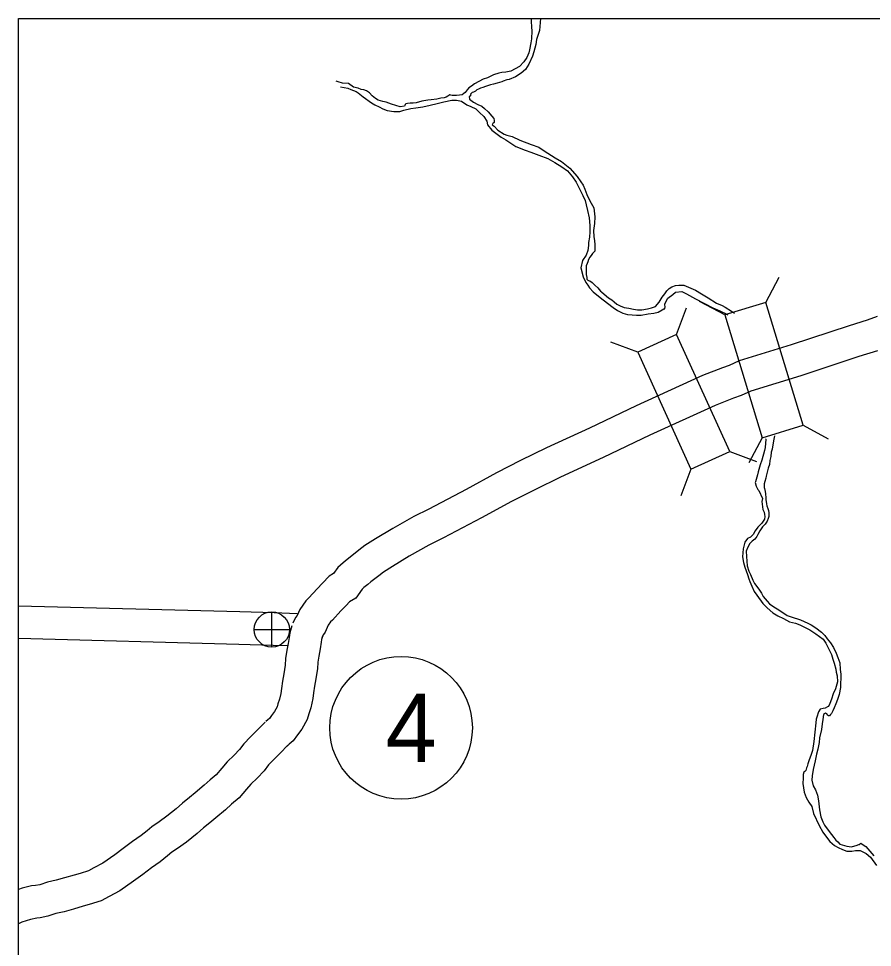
# Model space of a CAD drawing. Extents: x 79818 to 83933, y 50884 to 53307.
# Drawn here: x 80798.6 to 80904, y 53079 to 53193.5 of the extents above; entities that cross this region are included whole.
import ezdxf

# ---------------------------------------------------------------- set-up
doc = ezdxf.new("R2010")
doc.units = 0
for name, color, linetype in [('Level 10', 7, 'Continuous'), ('Level 20', 7, 'Continuous'), ('Level 26', 7, 'Continuous'), ('Level 27', 7, 'Continuous'), ('Level 9', 7, 'Continuous'), ('R_No Plot', 7, 'Continuous')]:
    doc.layers.add(name, color=color, linetype=linetype)

msp = doc.modelspace()

# ---------------------------------------------------------------- linework, layer by layer
at = {"layer": 'Level 10'}
for points in [[(80904.56, 53156.76), (80903.34, 53156.32), (80901.12, 53155.64), (80893.95, 53153.27), (80887.56, 53151.32), (80886.31, 53150.74), (80885.47, 53150.45), (80883.02, 53149.49), (80874.83, 53145.77), (80869.07, 53143.01), (80863.77, 53140.56), (80860.54, 53139), (80857.58, 53137.5), (80853.85, 53135.45), (80849.25, 53133.02), (80847.37, 53132.1), (80844.79, 53130.63), (80842.66, 53129.34), (80841.36, 53128.54), (80840.61, 53127.96)], [(80904.6, 53152.53), (80902.33, 53151.83), (80895.16, 53149.46), (80889, 53147.58), (80887.81, 53147.02), (80886.84, 53146.69), (80884.57, 53145.81), (80876.52, 53142.14), (80870.77, 53139.39), (80865.48, 53136.94), (80862.32, 53135.41), (80859.45, 53133.96), (80855.74, 53131.93), (80851.07, 53129.46), (80849.24, 53128.56), (80846.82, 53127.19), (80844.74, 53125.92), (80843.64, 53125.25), (80843.07, 53124.8)], [(80840.61, 53127.96), (80839.51, 53127.1), (80839.17, 53126.8), (80838.65, 53126.39), (80838.01, 53125.8), (80837.48, 53125.06), (80836.92, 53124.73), (80836.12, 53123.9), (80835.46, 53123.2), (80834.44, 53122.08), (80834.05, 53121.7), (80833.3, 53120.64), (80832.98, 53119.89), (80832.8, 53119.66), (80832.45, 53118.93)], [(80843.07, 53124.8), (80842.09, 53124.04), (80841.73, 53123.72), (80841.23, 53123.33), (80841.03, 53123.14), (80840.24, 53122.05), (80839.43, 53121.57), (80839.02, 53121.13), (80838.39, 53120.48), (80837.33, 53119.31), (80837.11, 53119.09), (80836.82, 53118.68), (80836.46, 53117.84), (80836.22, 53117.53), (80836.05, 53117.19)], [(80830.15, 53120.21), (80825.91, 53120.33), (80798.6, 53121.06)], [(80832.99, 53120.11), (80830.17, 53120.21)], [(80832.33, 53118.6), (80832.09, 53117.74), (80832.01, 53117.17), (80831.89, 53116.45), (80831.73, 53115.61), (80831.55, 53114.58), (80831.51, 53113.77), (80831.41, 53113.24), (80831.33, 53112.69), (80831.19, 53111.81), (80831.04, 53110.89), (80830.98, 53110.29), (80830.82, 53109.57), (80830.62, 53108.98), (80830.51, 53108.62), (80830.19, 53108.03), (80829.84, 53107.56), (80829.56, 53107.19), (80829.38, 53107.04), (80829.13, 53106.82)], [(80830.04, 53116.21), (80825.8, 53116.33), (80798.6, 53117.05)], [(80836.18, 53117.51), (80836.01, 53116.93), (80835.97, 53116.59), (80835.83, 53115.76), (80835.67, 53114.88), (80835.53, 53114.12), (80835.49, 53113.3), (80835.36, 53112.61), (80835.29, 53112.09), (80835.14, 53111.17), (80835.01, 53110.36), (80834.93, 53109.65), (80834.68, 53108.49), (80834.42, 53107.75), (80834.22, 53107.08), (80833.58, 53105.87), (80833.04, 53105.16), (80832.5, 53104.45), (80832, 53104.01), (80831.75, 53103.79)], [(80831.79, 53116.15), (80830.02, 53116.21)], [(80829.03, 53106.73), (80828.04, 53105.75), (80827.22, 53104.91), (80826.41, 53104.07), (80825.87, 53103.35), (80825.2, 53102.66), (80824.35, 53101.83), (80823.7, 53101.06), (80822.99, 53100.24), (80822.26, 53099.61), (80821.52, 53098.96), (80820.4, 53098.01), (80819.68, 53097.43), (80818.85, 53096.75), (80818.04, 53096.04), (80816.92, 53095.12), (80815.95, 53094.46), (80815.07, 53093.84), (80814.47, 53093.33), (80813.73, 53092.74), (80812.65, 53092.02), (80811.53, 53091.14), (80810.47, 53090.38), (80808.99, 53089.35), (80807.9, 53088.76), (80807.24, 53088.4), (80806.19, 53088.06), (80805.48, 53087.87), (80804.28, 53087.52), (80803.25, 53087.24), (80802.16, 53086.98), (80801.22, 53086.68), (80800.69, 53086.57), (80800.18, 53086.53), (80799.03, 53086.24), (80798.6, 53086.11)], [(80831.85, 53103.88), (80830.88, 53102.93), (80830.09, 53102.12), (80829.46, 53101.47), (80828.92, 53100.75), (80828.04, 53099.84), (80827.28, 53099.1), (80826.73, 53098.46), (80825.83, 53097.41), (80824.9, 53096.6), (80824.14, 53095.93), (80822.96, 53094.93), (80822.2, 53094.32), (80821.43, 53093.69), (80820.63, 53092.99), (80819.32, 53091.92), (80818.23, 53091.17), (80817.53, 53090.68), (80817, 53090.23), (80816.09, 53089.51), (80815, 53088.77), (80813.93, 53087.95), (80812.79, 53087.12), (80811.09, 53085.94), (80809.8, 53085.23), (80808.8, 53084.71), (80807.33, 53084.23), (80806.57, 53084.02), (80805.37, 53083.67), (80804.23, 53083.36), (80803.22, 53083.12), (80802.23, 53082.81), (80801.27, 53082.61), (80800.84, 53082.57), (80800.09, 53082.38), (80799.55, 53082.22), (80799.02, 53082.07), (80798.68, 53081.92), (80798.6, 53081.88)]]:
    msp.add_lwpolyline(points, dxfattribs=at)
at = {"layer": 'Level 20'}
for p, q in [((80890.82, 53158.51), (80892.47, 53161.61)), ((80885.77, 53156.97), (80882.66, 53158.62)), ((80879.82, 53154.54), (80881.06, 53157.84)), ((80875.02, 53152.36), (80871.72, 53153.59)), ((80895.44, 53143.36), (80898.55, 53141.7)), ((80890.39, 53141.82), (80888.73, 53138.71)), ((80886.38, 53140.13), (80889.68, 53138.89)), ((80881.58, 53137.94), (80880.35, 53134.64))]:
    msp.add_line(p, q, dxfattribs=at)
for points in [[(80885.77, 53156.97), (80890.39, 53141.82), (80895.44, 53143.36), (80890.82, 53158.51)], [(80886.38, 53140.13), (80879.82, 53154.54), (80875.02, 53152.36), (80881.58, 53137.94)]]:
    msp.add_lwpolyline(points, close=True, dxfattribs=at)
at = {"layer": 'Level 26'}
for p, q in [((80829.86, 53115.99), (80829.86, 53120.32)), ((80827.69, 53118.16), (80832.02, 53118.16))]:
    msp.add_line(p, q, dxfattribs=at)
msp.add_circle((80829.86, 53118.16), 2.17, dxfattribs=at)
at = {"layer": 'Level 27'}
msp.add_circle((80845.81, 53106.04), 8.8, dxfattribs=at)
at = {"layer": 'Level 9'}
for points in [[(80861.86, 53193.52), (80861.87, 53193.2), (80861.91, 53192.46), (80861.95, 53192.02), (80861.93, 53191.02), (80861.81, 53190.52), (80861.67, 53189.68), (80861.59, 53189.28), (80861.35, 53188.7), (80860.97, 53188.19), (80860.42, 53187.61), (80859.37, 53187.03), (80858.75, 53186.89), (80858.24, 53186.85), (80857.88, 53186.79), (80857.23, 53186.57), (80856.49, 53186.2), (80855.96, 53186.05), (80855.41, 53185.77), (80854.88, 53185.47), (80854.5, 53185.2), (80854.16, 53184.96), (80853.96, 53184.73), (80853.73, 53184.41), (80853.55, 53184.26), (80853.34, 53184.13), (80853.01, 53184.08), (80852.64, 53184.02), (80852.12, 53184.05), (80851.96, 53184.08), (80851.82, 53184.1), (80851.59, 53183.93), (80851.37, 53183.82), (80851.15, 53183.75), (80850.72, 53183.69), (80850.23, 53183.58), (80849.51, 53183.5), (80849.11, 53183.44), (80848.37, 53183.33), (80847.66, 53183.12), (80847.3, 53183.08), (80846.94, 53183.1), (80846.59, 53183.06), (80846.39, 53183), (80846.29, 53182.89), (80846.31, 53182.87), (80846.23, 53182.73), (80845.72, 53182.63), (80845.18, 53182.81), (80844.65, 53182.98), (80843.96, 53183.2), (80843.56, 53183.29), (80843, 53183.47), (80842.66, 53183.66), (80842.26, 53183.99), (80841.93, 53184.36), (80841.55, 53184.6), (80841.22, 53184.73), (80840.87, 53184.79), (80840.52, 53184.92), (80839.96, 53185.05), (80839.34, 53185.52), (80838.57, 53185.56), (80838.05, 53185.71), (80837.79, 53185.81)], [(80863.02, 53193.52), (80862.92, 53192.07), (80862.53, 53190.94), (80862.45, 53190.31), (80862.19, 53189.43), (80862.05, 53188.87), (80861.58, 53187.91), (80861.19, 53187.23), (80860.65, 53186.78), (80859.95, 53186.35), (80859.14, 53186), (80858.85, 53185.97), (80858.41, 53185.78), (80858.23, 53185.7), (80857.67, 53185.55), (80857.23, 53185.43), (80856.86, 53185.34), (80856.5, 53185.24), (80856.22, 53185.14), (80855.92, 53185.02), (80855.6, 53184.92), (80855.35, 53184.83), (80855.17, 53184.72), (80854.98, 53184.58), (80854.74, 53184.44), (80854.59, 53184.4), (80854.49, 53184.32), (80854.39, 53184.21), (80854.41, 53184.11), (80854.21, 53183.88), (80854.24, 53183.62), (80854.24, 53183.57), (80854.75, 53183.23), (80855.28, 53182.94), (80855.79, 53182.7), (80856.12, 53182.42), (80856.55, 53182), (80857, 53181.47), (80857.27, 53181.18), (80857.31, 53180.95), (80857.32, 53180.72), (80857.25, 53180.67), (80857.14, 53180.59), (80857.04, 53180.43), (80857.32, 53180.24), (80857.75, 53179.74), (80858.52, 53179.28), (80858.88, 53179.15), (80859.52, 53178.96), (80860.49, 53178.52), (80861.88, 53177.97), (80862.82, 53177.64), (80863.46, 53177.21), (80864.83, 53176.33), (80865.61, 53175.88), (80866.65, 53175.08), (80867.54, 53174.04), (80868, 53173.39), (80868.29, 53172.99), (80868.51, 53172.49), (80868.74, 53171.81), (80869.11, 53171.02), (80869.59, 53170.18), (80869.74, 53169.06), (80869.67, 53168.25), (80869.58, 53167.4), (80869.62, 53166.59), (80869.69, 53166.13), (80869.74, 53165.63), (80869.73, 53165.23), (80869.71, 53164.85), (80869.46, 53164.54), (80869.26, 53164.31), (80869.1, 53164.11), (80868.96, 53163.82), (80868.87, 53163.52), (80868.78, 53163.32), (80868.68, 53163.02), (80868.65, 53162.76), (80868.64, 53162.54), (80868.65, 53162.32), (80868.68, 53161.96), (80868.74, 53161.6), (80868.75, 53161.37), (80868.85, 53161.25), (80868.94, 53161.23), (80869.13, 53161.17), (80869.38, 53160.96), (80869.73, 53160.63), (80870.1, 53160.32), (80870.44, 53159.88), (80870.54, 53159.8), (80871.15, 53159.26), (80871.43, 53159.08), (80871.84, 53158.82), (80872.13, 53158.58), (80872.44, 53158.3), (80872.84, 53158.07), (80873.34, 53157.87), (80873.91, 53157.79), (80874.52, 53157.69)], [(80838.34, 53185.12), (80839.23, 53184.94), (80839.63, 53184.76), (80840.29, 53184.52), (80840.52, 53184.36), (80841.14, 53183.86), (80842.16, 53183.14), (80842.59, 53182.88), (80843.09, 53182.63), (80843.58, 53182.39), (80844.1, 53182.17), (80844.9, 53182.07), (80845.68, 53182.07), (80846.17, 53182.24), (80847.01, 53182.41), (80847.63, 53182.52), (80848.52, 53182.64), (80849.4, 53182.83), (80850.28, 53183.06), (80851.11, 53183.25), (80852.08, 53183.44), (80852.66, 53183.47), (80853.27, 53183.32), (80853.92, 53182.87), (80854.41, 53182.68), (80855.04, 53182.39), (80855.49, 53181.94), (80856.04, 53181.46), (80856.39, 53180.87), (80856.48, 53180.43), (80857.01, 53179.75), (80858.15, 53178.91), (80858.73, 53178.55), (80859.35, 53178.15), (80859.99, 53177.75), (80861.13, 53177.28), (80861.83, 53177.04), (80862.83, 53176.68), (80863.92, 53176.26), (80864.81, 53175.77), (80865.65, 53175.24), (80866.35, 53174.72), (80866.98, 53174), (80867.43, 53173.35), (80867.83, 53172.54), (80868.24, 53171.68), (80868.55, 53171.07), (80868.68, 53170.55), (80868.83, 53169.83), (80869.02, 53168.95), (80869.11, 53168.01), (80869.13, 53167.21), (80869.06, 53166.54), (80868.96, 53165.91), (80868.95, 53165.55), (80868.87, 53164.9), (80868.64, 53164.32), (80868.22, 53163.69), (80867.99, 53162.76), (80868.31, 53161.65), (80868.61, 53160.95), (80868.85, 53160.62), (80869.08, 53160.32), (80869.52, 53159.83), (80870.37, 53159.12), (80871.28, 53158.4), (80872.01, 53157.87), (80872.53, 53157.5), (80873.19, 53157.19), (80873.76, 53157.02), (80874.34, 53156.96), (80874.87, 53156.92), (80875.46, 53156.92), (80876.32, 53157.12), (80877.01, 53157.18), (80877.55, 53157.3), (80878.06, 53157.61), (80878.25, 53157.7), (80878.39, 53157.73), (80878.43, 53157.99), (80878.37, 53158.17), (80878.35, 53158.35), (80878.74, 53159.02), (80879.34, 53159.5), (80879.67, 53159.78), (80880.47, 53159.84), (80881.04, 53159.58), (80882.16, 53158.96), (80884.31, 53157.83), (80885.15, 53157.46), (80886.04, 53157.05), (80886.15, 53156.96)], [(80874.52, 53157.69), (80875, 53157.6), (80875.54, 53157.58), (80876.22, 53157.72), (80876.71, 53157.83), (80877.22, 53158), (80877.68, 53158.56), (80878.04, 53159.16), (80878.37, 53159.55), (80878.61, 53159.95), (80878.91, 53160.21), (80879.24, 53160.44), (80879.7, 53160.6), (80880.09, 53160.63), (80880.73, 53160.62), (80882.14, 53160.04), (80882.89, 53159.56), (80883.73, 53159.09), (80884.75, 53158.43), (80885.43, 53158.12), (80885.81, 53157.93), (80886.59, 53157.43), (80886.98, 53157.17)], [(80890.86, 53141.68), (80890.85, 53141.65), (80890.75, 53140.63), (80890.69, 53140.23), (80890.33, 53139.06), (80890.13, 53138.49), (80889.91, 53137.61), (80889.82, 53137.26), (80889.71, 53136.94), (80889.56, 53136.39), (80889.54, 53136.28), (80889.63, 53135.83), (80889.84, 53135.44), (80889.97, 53135.32), (80890.44, 53134.31), (80890.36, 53133.95), (80890.46, 53132.98), (80890.63, 53132.62), (80890.69, 53132.36), (80890.71, 53132.1), (80890.67, 53131.77), (80890.34, 53131.28), (80889.83, 53130.77), (80889.54, 53130.33), (80889.28, 53129.9), (80888.94, 53129.57), (80888.59, 53129.39), (80888.25, 53128.92), (80888.04, 53128.13), (80887.94, 53127.13), (80888.06, 53126.44), (80888.23, 53125.85), (80888.57, 53124.96), (80888.75, 53124.43), (80888.86, 53124.09), (80889.09, 53123.49), (80889.41, 53122.86), (80889.72, 53122.4), (80890.47, 53121.37), (80890.99, 53120.84), (80891.72, 53120.22), (80892.31, 53119.84), (80893.01, 53119.52), (80893.76, 53119.11), (80894.51, 53118.93), (80895.02, 53118.74), (80895.77, 53118.39), (80896.26, 53118.13), (80897.02, 53117.65), (80897.9, 53116.97), (80898.26, 53116.48), (80898.57, 53115.82), (80898.93, 53115.09), (80899.12, 53114.5), (80899.29, 53114.01), (80899.46, 53113.28), (80899.53, 53112.92), (80899.63, 53112.44), (80899.69, 53111.72), (80899.43, 53110.83), (80899.16, 53110.23), (80898.93, 53109.59), (80898.72, 53109.02), (80898.58, 53108.65), (80898.46, 53108.61), (80898.18, 53108.48), (80897.9, 53108.44), (80897.53, 53108.33), (80897.35, 53107.99), (80897.14, 53107.36), (80897.04, 53107.1), (80897.01, 53106.64), (80896.89, 53105.52), (80896.78, 53104.33), (80896.58, 53103.22), (80896.39, 53102.62), (80896.17, 53102.08), (80896.04, 53101.59), (80895.94, 53101.25), (80895.86, 53101.09), (80895.77, 53100.78), (80895.67, 53100.67), (80895.54, 53100.57), (80895.46, 53100.26), (80895.45, 53099.84), (80895.41, 53099.18), (80895.57, 53098.12), (80895.82, 53097.46), (80895.98, 53097.14), (80896.13, 53096.86), (80896.52, 53096.35), (80896.71, 53095.45), (80897.42, 53093.98), (80897.89, 53093.15), (80898.32, 53092.54)], [(80891.89, 53142.04), (80891.84, 53141.66), (80891.75, 53141.2), (80891.6, 53140.4), (80891.49, 53140.04), (80891.44, 53139.52), (80891.34, 53139.02), (80891.27, 53138.5), (80891.14, 53138.05), (80891.01, 53137.56), (80890.88, 53137.08), (80890.83, 53136.82), (80890.73, 53136.41), (80890.63, 53136.15), (80890.62, 53135.93), (80890.64, 53135.69), (80890.66, 53135.55), (80890.75, 53135.17), (80890.79, 53134.88), (80890.82, 53134.41), (80890.83, 53134.2), (80890.93, 53133.65), (80890.98, 53133.43), (80891.08, 53133.11), (80891.16, 53132.83), (80891.22, 53132.54), (80891.2, 53132.11), (80891.11, 53131.84), (80890.99, 53131.53), (80890.77, 53131.17), (80890.44, 53130.83), (80890.08, 53130.32), (80889.85, 53129.89), (80889.71, 53129.65), (80889.47, 53129.32), (80889.13, 53129.08), (80888.86, 53128.78), (80888.62, 53128.3), (80888.41, 53127.83), (80888.45, 53127.15), (80888.52, 53126.03), (80888.75, 53125.38), (80888.96, 53124.93), (80889.23, 53124.26), (80889.42, 53123.83), (80889.98, 53123.16), (80890.29, 53122.63), (80890.51, 53122.25), (80891, 53121.65), (80891.29, 53121.35), (80891.68, 53121.05), (80892.56, 53120.5), (80893.47, 53119.89), (80893.98, 53119.71), (80895.12, 53119.34), (80896.03, 53118.94)], [(80896.03, 53118.94), (80896.43, 53118.73), (80897.01, 53118.35), (80897.69, 53117.82), (80898.1, 53117.41), (80898.42, 53117), (80898.83, 53116.51), (80899.17, 53115.96), (80899.51, 53115.23), (80899.72, 53114.7), (80899.98, 53114.06), (80900.03, 53113.24), (80900.08, 53112.66), (80900.08, 53112.18), (80900.07, 53111.5), (80900.04, 53111), (80899.9, 53110.13), (80899.68, 53109.54), (80899.48, 53108.99), (80899.29, 53108.5), (80899.12, 53108.12), (80898.94, 53107.8), (80898.83, 53107.66), (80898.68, 53107.53), (80898.57, 53107.53), (80898.47, 53107.59), (80898.35, 53107.77), (80898.19, 53107.84), (80897.94, 53107.67), (80897.87, 53107.08), (80897.79, 53106.52), (80897.7, 53105.81), (80897.44, 53104.82), (80897.41, 53104.22), (80897.26, 53103.39), (80897.09, 53102.8), (80896.91, 53101.96), (80896.68, 53100.89), (80896.56, 53100.12), (80896.52, 53099.59), (80896.69, 53098.9), (80896.95, 53098.39), (80897.2, 53097.72), (80897.35, 53097.02), (80897.45, 53095.92), (80897.63, 53095.05), (80897.87, 53094.45), (80898.07, 53094.01), (80898.64, 53093.23), (80899.25, 53092.49), (80899.49, 53092.2), (80899.71, 53091.97), (80899.99, 53091.7), (80900.27, 53091.62), (80900.82, 53091.46), (80901.12, 53091.38), (80901.36, 53091.37), (80901.55, 53091.39), (80901.99, 53091.51), (80902.31, 53091.64), (80902.35, 53091.66), (80902.56, 53091.81), (80902.97, 53091.54), (80903.17, 53091.38), (80904.15, 53090.26)], [(80898.32, 53092.54), (80898.72, 53092.03), (80899.04, 53091.76), (80899.33, 53091.51), (80899.76, 53091.27), (80900.28, 53091.02), (80900.82, 53090.84), (80901.46, 53090.82), (80901.91, 53090.9), (80902.48, 53090.89), (80903.2, 53090.52), (80903.76, 53090.1), (80904.49, 53089.04)]]:
    msp.add_lwpolyline(points, dxfattribs=at)
at = {"layer": 'R_No Plot'}
msp.add_lwpolyline([(80798.6, 53193.52), (81459.98, 53193.52), (81459.98, 52610.7), (80798.6, 52610.7)], close=True, dxfattribs=at)
msp.add_lwpolyline([(80798.6, 53193.52), (81459.98, 53193.52), (81459.98, 52610.7), (80798.6, 52610.7)], close=True, dxfattribs=at)

# ---------------------------------------------------------------- texts
at = {"layer": 'Level 27'}
msp.add_text('4', height=8.45, dxfattribs=at).set_placement((80843.92, 53101.82))

doc.saveas('drawing.dxf')
